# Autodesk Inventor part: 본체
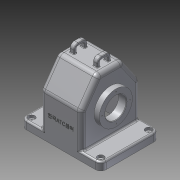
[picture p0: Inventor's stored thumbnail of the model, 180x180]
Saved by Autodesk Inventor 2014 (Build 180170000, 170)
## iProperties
Created: 2016-12
Part Number: 본체
Material: 알루미늄 6061
Document SubType Name: Modeling
Designer: NET
Density: 2.71 g/cm^3
Appearance: 알루미늄 - 평지
Mass: 1064.77 g
Surface Area: 1143.71 cm^2
Volume: 392.905 cm^3
Author: NET
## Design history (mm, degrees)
sketch "스케치1"
  geometry: L1 (0, 0)-(150, 0); L2 (150, 0)-(150, 15); L3 (150, 15)-(113.5, 15); L4 (113.5, 15)-(113.5, 125); L5 (113.5, 125)-(36.5, 125); L6 (36.5, 125)-(36.5, 15); L7 (36.5, 15)-(0, 15); L8 (0, 15)-(0, 0)
  constraints: 16 end point, 6 parallel, 2 equal length, 1 horizontal, 1 perpendicular
  dimensions: "d0" = 150 distance of L1.start L1.end; "d1" = 77 distance between parallel lines of L4 L6; "d2" = 125 distance between parallel lines of L1 L5; "d3" = 15 distance of L7.end L1.start
extrude "돌출1" new body sketch "스케치1" stored distance "d5" = 110; taper "d6" = 0 deg
sketch "스케치2"
  geometry: L1 (110, 110)-(0, 110) reference; L2 (0, 0)-(0, 110) reference; L3 (110, 110)-(110, 0) reference; L4 (0, 65)-(110, 65); L5 (110, 0)-(0, 0) reference; L6 (0, -15)-(0, 0) reference; L7 (110, -15)-(0, -15) reference; L8 (110, 0)-(110, -15) reference; L9 (0, 65)-(31.509, 110); L10 (110, 65)-(78.491, 110); L11 (0, 65)-(0, 110); L12 (0, 110)-(31.509, 110); L13 (78.491, 110)-(110, 110); L14 (110, 110)-(110, 65); 1 further point
  constraints: 14 end point, 4 collinear, 4 point on line, 1 equal length, 1 perpendicular
  dimensions: "d7" = 80 distance between parallel lines of L7 L4; "d8" = 35 deg angle of L2 L9
extrude "돌출2" cut sketch "스케치2" stored distance "d9" = 110; taper "d10" = 0 deg
node "작업 평면2"
sketch "스케치4"
  geometry: L1 (78.491, 110)-(110, 65) reference; L2 (110, 0)-(110, 65) reference; L3 (110, 0)-(0, 0) reference; L4 (0, 65)-(0, 0) reference; L5 (0, 65)-(31.509, 110) reference; L6 (78.491, 110)-(31.509, 110) reference; L7 (0, -15)-(110, -15) reference; L8 (0, 0)-(0, -15) reference; L9 (110, 0)-(0, 0) reference; L10 (110, -15)-(110, 0) reference; L11 (5, 63.424)-(34.112, 105); L12 (34.112, 105)-(75.888, 105); L13 (75.888, 105)-(105, 63.424); L14 (105, 63.424)-(105, -15); L15 (5, 63.424)-(5, -15); 1 further point
  constraints: 10 end point, 3 perpendicular, 2 parallel, 2 point on line
  dimensions: "d14" = 5 distance between parallel lines of L15 L4; "d15" = 5 distance between parallel lines of L2 L14; "d17" = 5 distance between parallel lines of L12 L6; "d18" = 5 distance between parallel lines of L11 L5; "d19" = 5 distance between parallel lines of L13 L1
extrude "돌출3" cut sketch "스케치4" stored distance "d20" = 67; taper "d21" = 0 deg
node "작업 평면3"
node "작업 평면4"
sketch "스케치5"
  geometry: L1 (0, 0)-(0, 65) reference; L2 (110, 65)-(110, 0) reference; L3 (31.509, 110)-(78.491, 110) reference; L4 (110, -15)-(0, -15) reference; L5 (0, 50)-(110, 50); L6 (55, -15)-(55, 110); C1 r 37.5 at (55, 50); 1 further point
  constraints: 4 end point, 3 point on line, 2 midpoint, 1 centre point, 1 coincident, 1 parallel
  dimensions: "d22" = 65 distance between parallel lines of L4 L5; "d23" = 75 diameter of C1
extrude "돌출4" join sketch "스케치5" distance "d24" = 5; taper "d25" = 0 deg
sketch "스케치7"
  geometry: C1 r 37.5 at (0, 0) reference; C2 r 20 at (0, 0); 1 further point
  constraints: 1 centre point, 1 coincident
  dimensions: "d26" = 40 diameter of C2
sketch "스케치6"
  geometry: L1 (5, -15)-(5, 63.424) reference; L2 (105, -15)-(5, -15) reference; L3 (105, 63.424)-(105, -15) reference; L4 (75.888, 105)-(105, 63.424) reference; L5 (34.112, 105)-(75.888, 105) reference; L6 (5, 63.424)-(34.112, 105) reference; C1 r 20 at (55, 50) reference; C2 r 27 at (55, 50); 1 further point
  constraints: 1 centre point, 1 coincident
  dimensions: "d27" = 54 diameter of C2
sketch "스케치8"
  geometry: L1 (31.5, 102.5)-(31.5, 27.5) reference; L2 (31.5, 65)-(55.5, 65); L3 (55.5, 92)-(41.5, 106); L4 (41.5, 106)-(41.5, 65); L5 (55.5, 92)-(55.5, 65); L6 (41.5, 65)-(55.5, 65); 1 further point
  constraints: 10 end point, 2 perpendicular, 1 collinear, 1 midpoint, 1 parallel, 1 point on line
  dimensions: "d31" = 54 diameter of L3.start L2; "d32" = 45 deg angle of L5 L3; "d33" = 24 distance between parallel lines of L1 L5; "d34" = 14 distance between parallel lines of L5 L4
revolve "회전1" sketch "스케치8" stored, may be unused: angle "d35" = 90 deg
sketch "스케치9"
  geometry: C1 r 37.5 at (55, 50) reference; C2 r 37.5 at (55, 50) reference; C3 r 31 at (55, 50); 1 further point
  constraints: 1 centre point, 1 coincident
  dimensions: "d36" = 62 diameter of C3
extrude "돌출5" join sketch "스케치9" distance "d37" = 10; taper "d38" = 0 deg
extrude "돌출6" cut sketch "스케치7" stored distance "d39" = 10; taper "d40" = 0 deg
sketch "스케치10"
  geometry: L1 (77, 0)-(0, 0) reference; L2 (0, 0)-(0, -46.981) reference; L3 (0, -46.981)-(77, -46.981) reference; L4 (77, 0)-(77, -46.981) reference; L5 (0, -23.491)-(77, -23.491); L6 (38.5, 0)-(38.5, -46.981); L7 (56.5, -10.991)-(56.5, -35.991); L8 (20.5, -10.991)-(20.5, -35.991); L9 (64.5, -35.991)-(64.5, -10.991); L10 (12.5, -10.991)-(12.5, -35.991); L11 (12.5, -10.991)-(20.5, -10.991); L12 (12.5, -35.991)-(20.5, -35.991); L13 (56.5, -10.991)-(64.5, -10.991); L14 (56.5, -35.991)-(64.5, -35.991); 7 further points
  constraints: 20 end point, 10 midpoint, 10 parallel, 4 horizontal alignment, 1 perpendicular
  dimensions: "d44" = 36 distance between parallel lines of L7 L8; "d45" = 18 distance between parallel lines of L7 L6; "d46" = 52 distance between parallel lines of L9 L10; "d47" = 26 distance between parallel lines of L9 L6; "d48" = 25 distance of L10.start L10.end
extrude "돌출7" join sketch "스케치10" distance "d49" = 15; taper "d50" = 0 deg
sketch "스케치11"
  geometry: L1 (25, 0)-(25, 15) reference; L2 (0, 15)-(25, 15) reference; L3 (35.991, 0)-(-10.991, 0) reference; L4 (5, 0)-(20, 0); L5 (20, 0)-(20, 10); L6 (20, 10)-(5, 10); L7 (5, 10)-(5, 0); 1 further point
  constraints: 8 end point, 2 parallel, 1 horizontal, 1 perpendicular, 1 point on line
  dimensions: "d51" = 5 distance between parallel lines of L6 L2; "d52" = 15 distance of L5.end L6.end; "d53" = 5 distance between parallel lines of L1 L5
extrude "돌출8" cut sketch "스케치11" stored distance "d54" = 15; taper "d55" = 0 deg
fillet "모깎기1" dims "d56" = 10
sketch "스케치13"
  geometry: A1 r 10 centre (-26.5, 100) between (-26.5, 110) and (-36.5, 100) reference; A2 r 10 centre (-26.5, 10) between (-36.5, 10) and (-26.5, 0) reference; 3 further points
  constraints: 2 coincident
hole "구멍1" sketch "스케치13" at (-26.5, 100), (-26.5, 10) diameter "d57" = 5; stored, may be unused: countersink angle "d61" = 90 deg, drill point angle "d63" = 118 deg; dims "d58" = 6, "d59" = 12, "d60" = 5, "d62" = 8
sketch "스케치14"
  geometry: C1 r 20 at (0, 0) reference; 2 further points
  constraints: 1 vertical alignment
  dimensions: "d64" = 29 distance of C1.centre point (0, 29)
hole "구멍2" sketch "스케치14" at (0, 29) diameter "d65" = 2.459; stored, may be unused: countersink angle "d69" = 90 deg, drill point angle "d71" = 118 deg; dims "d66" = 6, "d67" = 12, "d68" = 5, "d70" = 8
sketch "스케치15"
  geometry: C1 r 20 at (0, 0) reference; 2 further points
  constraints: 1 vertical alignment
  dimensions: "d75" = 26 distance of C1.centre point (0, 26)
hole "구멍3" sketch "스케치15" at (0, 26) diameter "d76" = 2.459; stored, may be unused: countersink angle "d80" = 90 deg, drill point angle "d82" = 118 deg; dims "d77" = 6, "d78" = 12, "d79" = 5, "d81" = 8
sketch "스케치16"
  geometry: L1 (10, 0)-(140, 0) reference; L2 (36.5, 80)-(36.5, 15) reference; 2 further points
  constraints: 1 other
  dimensions: "d86" = 38.5 distance from line of point (75, 45) L2; "d87" = 45 distance from line of point (75, 45) L1
feature "엠보싱1" sketch "스케치16" dims "d0" = 150, "d1" = 77, "d2" = 125, "d3" = 15, "d88" = 0.5, "d89" = 0
fillet "모깎기2" dims "d90" = 10
fillet "모깎기3" dims "d91" = 10
fillet "모깎기4" dims "d92" = 8
fillet "모깎기5" dims "d93" = 8
chamfer "모따기1" distance "d94" = 1; stored, may be unused: second distance "d95" = 2, angle "d96" = 45 deg
chamfer "모따기2" distance "d97" = 1; stored, may be unused: second distance "d98" = 2, angle "d99" = 45 deg
fillet "모깎기6" dims "d100" = 3
fillet "모깎기7" dims "d101" = 3
fillet "모깎기8" dims "d102" = 1
fillet "모깎기9" dims "d103" = 3
fillet "모깎기10" dims "d104" = 3
fillet "모깎기11" dims "d105" = 3
fillet "모깎기12" dims "d106" = 1
node "솔리드1"
mirror "대칭1"
pattern_circular "원형 패턴1" dims angle "d73" = 360 deg
pattern_circular "원형 패턴2" dims angle "d84" = 360 deg
node "투영된 루프1"
node "투영된 루프2"
node "투영된 루프3"
node "투영된 루프4"
